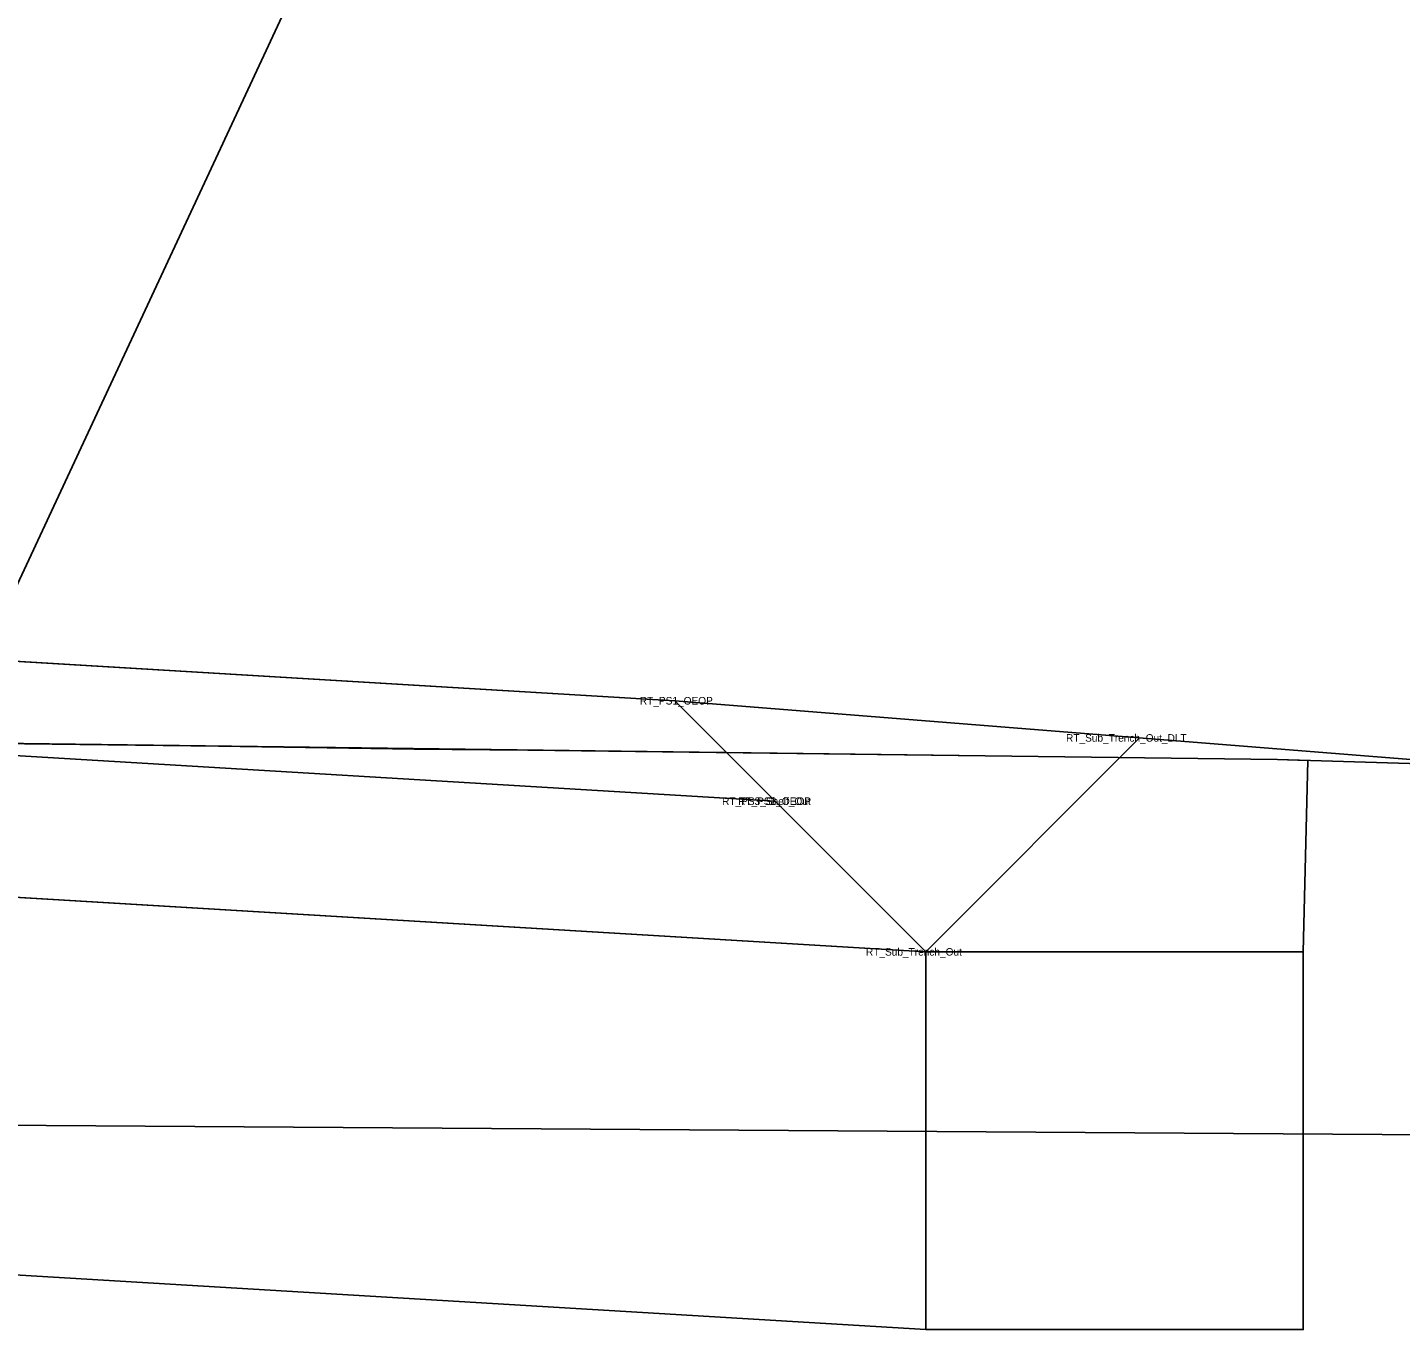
# Model space of a CAD drawing. Extents: x -516 to 303, y -10 to 5017.
# Drawn here: x 162.285 to 165.923, y 3003.089 to 3006.537 of the extents above; entities that cross this region are included whole.
import ezdxf

# ---------------------------------------------------------------- set-up
doc = ezdxf.new("R2010")
doc.units = 0
for name, color, linetype in [('Exist XS Ground Line', 7, 'Continuous'), ('Prop CMT Pvmt Surface Shoulder', 7, 'Continuous'), ('Prop CMT Shld Paved Course 1', 7, 'Continuous'), ('Prop CMT Shld Paved Course 2', 7, 'Continuous'), ('Prop CMT Shld Paved Course 3', 7, 'Continuous'), ('Prop CMT Slope Grass', 7, 'Continuous'), ('Prop CMT Subgrade Earthwork', 7, 'Continuous'), ('Prop Road Sect_ Material - Contact (General - Major)', 7, 'Continuous'), ('Prop Road Sect_ Misc - Drafting Aid (solid line)', 7, 'Continuous'), ('Prop Road Sect_ Misc - Drafting Aid (Tx - small)', 7, 'Continuous'), ('Prop Road Sect_ Recs - UC Shallow (Outline)', 7, 'Continuous'), ('Prop Road Sect_ Recs - UC Shallow (Pattern)', 7, 'Continuous'), ('Scratch_Level_0', 7, 'Continuous')]:
    doc.layers.add(name, color=color, linetype=linetype)

msp = doc.modelspace()

# ---------------------------------------------------------------- linework, layer by layer
at = {"layer": 'Exist XS Ground Line'}
msp.add_lwpolyline([(127.6717, 3004.8956), (129.9724, 3004.8801), (136.1955, 3004.6894), (149.2025, 3004.7517), (149.5824, 3004.7536), (150.2842, 3004.7329), (152.2526, 3004.7198), (152.8486, 3004.7093), (154.5021, 3004.7218), (155.1545, 3004.7264), (155.8812, 3004.7161), (157.8066, 3004.6912), (159.4913, 3004.6732), (160.5369, 3004.6613), (161.7241, 3004.6468), (162.7917, 3004.6337), (163.3101, 3004.6258), (163.611, 3004.6229), (164.8225, 3004.6077), (165.5966, 3004.5986), (166.1809, 3004.5801)], dxfattribs=at)
at = {"layer": 'Prop CMT Pvmt Surface Shoulder'}
msp.add_line((162, 3004.874), (164, 3004.754), dxfattribs=at)
at = {"layer": 'Prop CMT Shld Paved Course 1'}
for points in [[(162, 3004.874), (164, 3004.754), (164.266, 3004.488)], [(164.266, 3004.488), (162, 3004.624)]]:
    msp.add_lwpolyline(points, dxfattribs=at)
at = {"layer": 'Prop CMT Shld Paved Course 2'}
for points in [[(162, 3004.624), (164.266, 3004.488)], [(164.266, 3004.488), (162, 3004.624)], [(164.266, 3004.488), (164.266, 3004.488)]]:
    msp.add_lwpolyline(points, dxfattribs=at)
at = {"layer": 'Prop CMT Shld Paved Course 3'}
for points in [[(162, 3004.624), (164.266, 3004.488)], [(164.266, 3004.488), (164.266, 3004.488)], [(164.266, 3004.488), (164.6649, 3004.0891)], [(164.6649, 3004.0891), (162, 3004.249)]]:
    msp.add_lwpolyline(points, dxfattribs=at)
at = {"layer": 'Prop CMT Slope Grass'}
msp.add_line((164, 3004.754), (170, 3004.274), dxfattribs=at)
at = {"layer": 'Prop CMT Subgrade Earthwork'}
for p, q in [((164.6649, 3004.0891), (165.2313, 3004.6555)), ((162, 3004.249), (164.6649, 3004.0891))]:
    msp.add_line(p, q, dxfattribs=at)
at = {"layer": 'Prop Road Sect_ Material - Contact (General - Major)'}
msp.add_line((178.8965, 3003.5176), (2.4565, 3004.7053), dxfattribs=at)
at = {"layer": 'Prop Road Sect_ Misc - Drafting Aid (solid line)'}
for p, q in [((164.6649, 3004.0891), (164.6649, 3003.0891)), ((164.6649, 3004.0891), (165.6649, 3004.0891)), ((165.6649, 3004.0891), (165.6649, 3003.0891))]:
    msp.add_line(p, q, dxfattribs=at)
at = {"layer": 'Prop Road Sect_ Misc - Drafting Aid (Tx - small)'}
msp.add_line((163.9214, 3008.6281), (161.8797, 3004.2503), dxfattribs=at)
at = {"layer": 'Prop Road Sect_ Recs - UC Shallow (Outline)'}
msp.add_lwpolyline([(165.6772, 3004.596), (165.5966, 3004.5986), (164.8225, 3004.6077), (161.7224, 3004.6479), (160.5369, 3004.6613), (159.4913, 3004.6732), (157.8066, 3004.6912), (155.8812, 3004.7161), (155.1545, 3004.7264), (154.5021, 3004.7218), (152.8486, 3004.7093), (149.9985, 3004.7392), (148, 3004.746), (145.4104, 3004.7336), (144.4104, 3004.7288), (144.4104, 3004.2444), (145.4104, 3004.2444), (148, 3004.089), (162, 3003.249), (164.6649, 3003.0891), (165.6649, 3003.0891), (165.6649, 3004.0891), (165.6772, 3004.596)], dxfattribs=at)
at = {"layer": 'Prop Road Sect_ Recs - UC Shallow (Pattern)'}
msp.add_lwpolyline([(165.6772, 3004.596), (165.5966, 3004.5986), (164.8225, 3004.6077), (161.7224, 3004.6479), (160.5369, 3004.6613), (159.4913, 3004.6732), (157.8066, 3004.6912), (155.8812, 3004.7161), (155.1545, 3004.7264), (154.5021, 3004.7218), (152.8486, 3004.7093), (149.9985, 3004.7392), (148, 3004.746), (145.4104, 3004.7336), (144.4104, 3004.7288), (144.4104, 3004.2444), (145.4104, 3004.2444), (148, 3004.089), (162, 3003.249), (164.6649, 3003.0891), (165.6649, 3003.0891), (165.6649, 3004.0891), (165.6772, 3004.596)], dxfattribs=at)

# ---------------------------------------------------------------- texts
at = {"layer": 'Scratch_Level_0'}
for s, p in [('RT_PS1_OEOP', (163.9076, 3004.744)), ('RT_Sub_Trench_Out_DLT', (165.0365, 3004.6455)), ('RT_PS3_Shelf_Out', (164.1253, 3004.478)), ('RT_PS3_OEOP', (164.1678, 3004.478)), ('RT_PS2_OEOP', (164.1678, 3004.478)), ('RT_Sub_Trench_Out', (164.5065, 3004.0791))]:
    msp.add_text(s, height=0.02, dxfattribs=at).set_placement(p)

doc.saveas('drawing.dxf')
